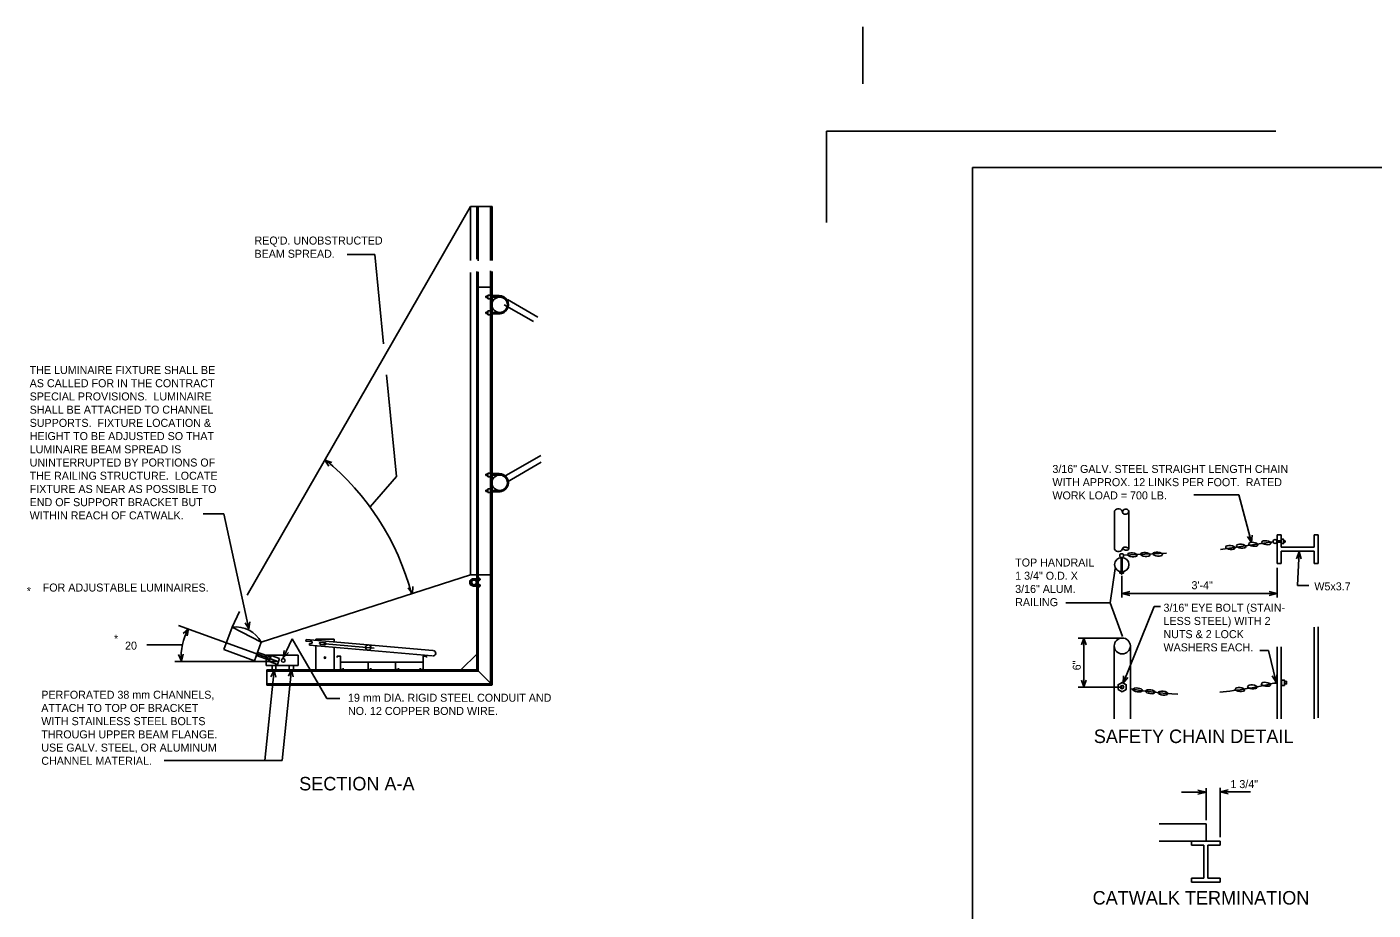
# Model space of a CAD drawing. Extents: x 2472.79 to 2482.44, y 2457.5 to 2462.64.
# Drawn here: x 2472.791 to 2476.659, y 2460.096 to 2462.635 of the extents above; entities that cross this region are included whole.
import ezdxf

# ---------------------------------------------------------------- set-up
doc = ezdxf.new("R2010")
doc.units = 0
doc.layers.add('Level 1', color=7, linetype='Continuous')
doc.layers.add('Level 2', color=7, linetype='Continuous')

msp = doc.modelspace()

# ---------------------------------------------------------------- linework, layer by layer
at = {"layer": 'Level 1'}
for p, q in [((2476.3796, 2462.3356), (2475.0881, 2462.3356)), ((2475.0881, 2462.3356), (2475.0881, 2462.0726)), ((2475.5081, 2457.8211), (2475.5081, 2462.2306)), ((2482.0963, 2462.2306), (2475.5081, 2462.2306)), ((2474.0655, 2462.1183), (2474.1272, 2462.1183)), ((2474.0655, 2461.963), (2474.0655, 2462.1183)), ((2474.0831, 2461.9676), (2474.0831, 2462.1183)), ((2474.0873, 2461.9621), (2474.0873, 2462.1183)), ((2474.1229, 2461.9639), (2474.1229, 2462.1183)), ((2474.1272, 2461.9639), (2474.1272, 2462.1183)), ((2474.0655, 2461.0599), (2474.0655, 2461.9292)), ((2474.0831, 2461.0599), (2474.0831, 2461.932)), ((2474.0873, 2461.0599), (2474.0873, 2461.9311)), ((2474.1229, 2461.0599), (2474.1229, 2461.9338)), ((2474.1272, 2461.0599), (2474.1272, 2461.932)), ((2474.083, 2460.787), (2474.083, 2461.8871)), ((2474.083, 2461.8871), (2474.1271, 2461.8871)), ((2474.0873, 2460.7828), (2474.0873, 2461.8871)), ((2474.109, 2461.8609), (2474.109, 2461.8567)), ((2474.109, 2461.8609), (2474.1155, 2461.8609)), ((2474.1155, 2461.8641), (2474.1216, 2461.8641)), ((2474.1155, 2461.8641), (2474.1155, 2461.8535)), ((2474.1229, 2460.7423), (2474.1229, 2461.8871)), ((2474.1257, 2461.8625), (2474.1477, 2461.8625)), ((2474.1271, 2460.7429), (2474.1271, 2461.8871)), ((2474.109, 2461.8567), (2474.1155, 2461.8567)), ((2474.1155, 2461.8535), (2474.1216, 2461.8535)), ((2474.1284, 2461.8583), (2474.1505, 2461.8583)), ((2474.1623, 2461.8359), (2474.2459, 2461.7877)), ((2474.1712, 2461.8512), (2474.2592, 2461.8004)), ((2474.109, 2461.8151), (2474.109, 2461.8109)), ((2474.109, 2461.8151), (2474.1155, 2461.8151)), ((2474.109, 2461.8109), (2474.1155, 2461.8109)), ((2474.1155, 2461.8183), (2474.1216, 2461.8183)), ((2474.1155, 2461.8183), (2474.1155, 2461.8077)), ((2474.1155, 2461.8077), (2474.1216, 2461.8077)), ((2474.1279, 2461.8099), (2474.1501, 2461.8099)), ((2474.1284, 2461.8142), (2474.1504, 2461.8142)), ((2474.1623, 2461.3422), (2474.2672, 2461.4027)), ((2474.1712, 2461.3269), (2474.2688, 2461.3833)), ((2474.109, 2461.3492), (2474.109, 2461.3449)), ((2474.109, 2461.3492), (2474.1155, 2461.3492)), ((2474.109, 2461.3449), (2474.1155, 2461.3449)), ((2474.1155, 2461.3523), (2474.1216, 2461.3523)), ((2474.1155, 2461.3523), (2474.1155, 2461.3418)), ((2474.1155, 2461.3418), (2474.1216, 2461.3418)), ((2474.1257, 2461.3507), (2474.1477, 2461.3507)), ((2474.1284, 2461.3465), (2474.1505, 2461.3465)), ((2474.109, 2461.3034), (2474.109, 2461.2991)), ((2474.109, 2461.3034), (2474.1155, 2461.3034)), ((2474.109, 2461.2991), (2474.1155, 2461.2991)), ((2474.1155, 2461.3066), (2474.1216, 2461.3066)), ((2474.1155, 2461.3066), (2474.1155, 2461.296)), ((2474.1155, 2461.296), (2474.1216, 2461.296)), ((2474.1279, 2461.2982), (2474.1501, 2461.2982)), ((2474.1284, 2461.3024), (2474.1504, 2461.3024)), ((2475.9161, 2461.1331), (2475.9161, 2461.2433)), ((2475.9572, 2461.1331), (2475.9572, 2461.2417)), ((2476.3837, 2461.092), (2476.3837, 2461.1743)), ((2476.395, 2461.1743), (2476.3837, 2461.1743)), ((2476.395, 2461.1743), (2476.395, 2461.139)), ((2476.5014, 2461.1743), (2476.4901, 2461.1743)), ((2476.4901, 2461.1743), (2476.4901, 2461.139)), ((2476.5014, 2461.092), (2476.5014, 2461.1743)), ((2476.3825, 2461.157), (2476.3951, 2461.157)), ((2476.3825, 2461.1533), (2476.3949, 2461.1533)), ((2476.4901, 2461.139), (2476.395, 2461.139)), ((2476.395, 2461.092), (2476.395, 2461.1273)), ((2476.4901, 2461.1273), (2476.395, 2461.1273)), ((2476.4067, 2461.157), (2476.4016, 2461.157)), ((2476.4067, 2461.1533), (2476.402, 2461.1533)), ((2476.4067, 2461.157), (2476.4067, 2461.1533)), ((2476.4901, 2461.092), (2476.4901, 2461.1273)), ((2475.935, 2461.1094), (2475.935, 2461.0688)), ((2475.9381, 2461.1089), (2475.9381, 2461.0683)), ((2476.395, 2461.092), (2476.3837, 2461.092)), ((2476.5014, 2461.092), (2476.4901, 2461.092)), ((2474.0655, 2461.0599), (2474.1272, 2461.0599)), ((2474.0742, 2461.0485), (2474.083, 2461.0485)), ((2474.083, 2460.7958), (2474.083, 2461.0589)), ((2474.0901, 2461.051), (2474.0873, 2461.051)), ((2474.0901, 2461.051), (2474.0901, 2461.0424)), ((2474.0931, 2461.0485), (2474.0901, 2461.0485)), ((2474.0931, 2461.0485), (2474.0931, 2461.0454)), ((2474.0742, 2461.0454), (2474.083, 2461.0454)), ((2474.0742, 2461.0305), (2474.083, 2461.0305)), ((2474.0742, 2461.0273), (2474.083, 2461.0273)), ((2474.0901, 2461.0424), (2474.0855, 2461.0424)), ((2474.0901, 2461.0243), (2474.0855, 2461.0243)), ((2474.0901, 2461.0331), (2474.0856, 2461.0331)), ((2474.0931, 2461.0454), (2474.0901, 2461.0454)), ((2474.0901, 2461.0243), (2474.0901, 2461.0331)), ((2474.0931, 2461.0305), (2474.0901, 2461.0305)), ((2474.0931, 2461.0273), (2474.0901, 2461.0273)), ((2474.0931, 2461.0273), (2474.0931, 2461.0305)), ((2473.3564, 2460.8445), (2473.38, 2460.9093)), ((2473.4639, 2460.8656), (2473.38, 2460.9093)), ((2476.4901, 2460.6455), (2476.4901, 2460.9089)), ((2476.5014, 2460.6484), (2476.5014, 2460.9104)), ((2473.4445, 2460.8125), (2473.4639, 2460.8656)), ((2473.593, 2460.8739), (2473.5925, 2460.869)), ((2473.6079, 2460.8676), (2473.5925, 2460.869)), ((2473.593, 2460.8739), (2473.9567, 2460.8421)), ((2473.603, 2460.8625), (2473.6026, 2460.8576)), ((2473.6026, 2460.8576), (2473.9553, 2460.8267)), ((2473.6208, 2460.8746), (2473.655, 2460.8746)), ((2473.6208, 2460.8746), (2473.649, 2460.8746)), ((2473.6208, 2460.8746), (2473.6396, 2460.8746)), ((2473.6208, 2460.8746), (2473.6208, 2460.8713)), ((2473.6208, 2460.7864), (2473.6208, 2460.8557)), ((2473.6737, 2460.8746), (2473.655, 2460.8746)), ((2473.6737, 2460.8746), (2473.655, 2460.8746)), ((2473.6737, 2460.8746), (2473.6737, 2460.867)), ((2475.9151, 2460.6455), (2475.9151, 2460.8552)), ((2475.9151, 2460.6455), (2475.9151, 2460.8552)), ((2475.9614, 2460.6455), (2475.9614, 2460.8552)), ((2473.4445, 2460.8125), (2473.3564, 2460.8445)), ((2473.4874, 2460.8141), (2473.4502, 2460.8276)), ((2473.4903, 2460.8235), (2473.4539, 2460.8367)), ((2473.4785, 2460.8287), (2473.5698, 2460.8287)), ((2473.4785, 2460.7994), (2473.4785, 2460.8287)), ((2473.4868, 2460.8109), (2473.4929, 2460.8275)), ((2473.5166, 2460.8189), (2473.4929, 2460.8275)), ((2473.5105, 2460.8023), (2473.5166, 2460.8189)), ((2473.5698, 2460.7994), (2473.5698, 2460.8287)), ((2473.6737, 2460.7864), (2473.6737, 2460.8514)), ((2474.083, 2460.8311), (2474.0389, 2460.787)), ((2476.3837, 2460.6455), (2476.3837, 2460.8529)), ((2476.395, 2460.6455), (2476.395, 2460.8529)), ((2473.4785, 2460.7994), (2473.5698, 2460.7994)), ((2473.4796, 2460.7864), (2474.083, 2460.7864)), ((2473.4796, 2460.7423), (2473.4796, 2460.7864)), ((2473.4796, 2460.7822), (2474.0873, 2460.7822)), ((2473.5105, 2460.8023), (2473.4868, 2460.8109)), ((2473.4949, 2460.7865), (2473.4949, 2460.7994)), ((2473.506, 2460.7865), (2473.506, 2460.7994)), ((2473.5444, 2460.7865), (2473.5444, 2460.7994)), ((2473.5562, 2460.7865), (2473.5562, 2460.7994)), ((2473.6913, 2460.8085), (2473.9296, 2460.8085)), ((2473.9037, 2460.7864), (2473.983, 2460.7864)), ((2473.9037, 2460.7822), (2474.0178, 2460.7822)), ((2474.083, 2460.787), (2474.1271, 2460.7429)), ((2473.4796, 2460.7466), (2474.1229, 2460.7466)), ((2473.4796, 2460.7423), (2474.1271, 2460.7423)), ((2476.3837, 2460.7483), (2476.3736, 2460.7483)), ((2476.1368, 2460.3435), (2476.0442, 2460.3435)), ((2476.1368, 2460.3435), (2476.1797, 2460.3435)), ((2476.1368, 2460.2934), (2476.0442, 2460.2934)), ((2476.1368, 2460.2934), (2476.1368, 2460.2821)), ((2476.2192, 2460.2934), (2476.1368, 2460.2934)), ((2476.1368, 2460.2821), (2476.1722, 2460.2821)), ((2476.1722, 2460.2821), (2476.1722, 2460.187)), ((2476.2192, 2460.2821), (2476.1839, 2460.2821)), ((2476.1839, 2460.2821), (2476.1839, 2460.187)), ((2476.2192, 2460.2934), (2476.2192, 2460.2821)), ((2476.1368, 2460.187), (2476.1368, 2460.1758)), ((2476.1368, 2460.187), (2476.1722, 2460.187)), ((2476.2192, 2460.1758), (2476.1368, 2460.1758)), ((2476.2192, 2460.187), (2476.1839, 2460.187)), ((2476.2192, 2460.187), (2476.2192, 2460.1758))]:
    msp.add_line(p, q, dxfattribs=at)
for points in [[(2476.3949, 2461.1497), (2476.4018, 2461.1497), (2476.4018, 2461.1618), (2476.3949, 2461.1618)], [(2475.9309, 2461.0687), (2475.9419, 2461.0687), (2475.9419, 2461.0645), (2475.9309, 2461.0645)], [(2475.9346, 2461.0683), (2475.9389, 2461.0683), (2475.9389, 2461.0683), (2475.9346, 2461.0683)], [(2475.9376, 2460.7233), (2475.9494, 2460.7299), (2475.9496, 2460.7434), (2475.938, 2460.7504), (2475.9262, 2460.7438), (2475.926, 2460.7302)], [(2476.3956, 2460.7415), (2476.4044, 2460.7415), (2476.4044, 2460.7571), (2476.3956, 2460.7571)], [(2476.4046, 2460.7461), (2476.4105, 2460.7461), (2476.4105, 2460.7534), (2476.4046, 2460.7534)]]:
    msp.add_lwpolyline(points, close=True, dxfattribs=at)
for points in [[(2475.9408, 2461.1165), (2476.0656, 2461.1215)], [(2475.9356, 2461.0642), (2475.9356, 2461.062), (2475.9374, 2461.062), (2475.9374, 2461.0642)], [(2473.6913, 2460.8085), (2473.6913, 2460.8261), (2473.6826, 2460.8261), (2473.6826, 2460.8219)], [(2473.9296, 2460.8085), (2473.9296, 2460.8261), (2473.9384, 2460.8261), (2473.9384, 2460.8219)], [(2473.6913, 2460.8085), (2473.6913, 2460.787), (2473.6998, 2460.787), (2473.6998, 2460.7912)], [(2473.6913, 2460.8085), (2473.6913, 2460.787), (2473.6998, 2460.787), (2473.6998, 2460.7912)], [(2473.7708, 2460.8085), (2473.7708, 2460.787), (2473.7792, 2460.787), (2473.7792, 2460.7912)], [(2473.8502, 2460.8085), (2473.8502, 2460.787), (2473.8586, 2460.787), (2473.8586, 2460.7912)], [(2473.9296, 2460.8085), (2473.9296, 2460.787), (2473.9211, 2460.787), (2473.9211, 2460.7912)]]:
    msp.add_lwpolyline(points, dxfattribs=at)
for centre, major_axis, start_param, end_param in [((2474.1477, 2461.8362), (-0.0263, 0), 1.570796, 4.712389), ((2474.1492, 2461.8362), (-0.0221, 0), 1.570796, 4.712389), ((2474.1477, 2461.3245), (-0.0263, 0), 1.570796, 4.712389), ((2474.1492, 2461.3245), (-0.0221, 0), 1.570796, 4.712389), ((2475.9267, 2461.2382), (-0.0118, 0), 3.176119, 5.840553), ((2475.948, 2461.2391), (0.00957, 0), 0.273424, 3.195008), ((2475.9473, 2461.2436), (-0.0101, 0), 0.517939, 2.950494), ((2475.9271, 2461.1386), (-0.0123, 0), 0.467275, 2.979388), ((2475.9467, 2461.1269), (-0.0122, 0), 3.667658, 5.365602), ((2475.9496, 2461.1417), (0.0116, 0), 3.600977, 5.432283), ((2474.0739, 2461.0379), (0.0106, 0), 1.542929, 4.740256), ((2474.0738, 2461.0379), (0.00745, 0), 1.515065, 4.76812), ((2473.3906, 2460.8274), (-0.0826, 0), 3.622274, 4.841499), ((2473.6077, 2460.8649), (-0.00275, 0), 1.48353, 4.625122), ((2475.9382, 2460.8548), (0.0232, 0), 0.01739, 3.126763), ((2475.9382, 2460.8548), (0.0232, 0), 0.01739, 3.126763), ((2475.9382, 2460.8556), (0.0232, 0), 3.156422, 6.265796), ((2473.9575, 2460.8344), (-0.00772, 0), 1.500919, 4.610293), ((2476.1329, 2461.7165), (-0.998, 0), 1.656478, 1.814374), ((2476.1433, 2461.7132), (-0.998, 0), 1.38791, 1.525517)]:
    msp.add_ellipse(centre, major_axis=major_axis, ratio=0.9996, start_param=start_param, end_param=end_param, dxfattribs=at)
for centre, major_axis, ratio in [((2474.1492, 2461.8362), (0.0221, 0), 0.9996), ((2474.1492, 2461.8362), (0.0221, 0), 0.9996), ((2474.1492, 2461.3245), (0.0221, 0), 0.9996), ((2474.1492, 2461.3245), (0.0221, 0), 0.9996), ((2476.0044, 2461.1181), (-0.0135, 0.0015), 0.412607), ((2476.0401, 2461.1189), (-0.0135, 0.0015), 0.412607), ((2476.2489, 2461.1382), (-0.0135, 0.0015), 0.412607), ((2476.2799, 2461.142), (-0.0135, 0.0015), 0.412607), ((2476.3149, 2461.1474), (-0.0135, 0.0015), 0.412607), ((2476.3522, 2461.1521), (-0.0135, 0.0015), 0.412607), ((2476.377, 2461.1554), (0.00548, 0), 0.9996), ((2475.9367, 2461.0889), (0.0206, 0), 0.9996), ((2475.9365, 2461.1149), (0.00548, 0), 0.9996), ((2475.9671, 2461.1173), (-0.0135, 0.0015), 0.412607), ((2474.0756, 2461.0379), (0.00662, 0), 0.9996), ((2473.6472, 2460.8614), (0.0022, 0), 0.9996), ((2473.6472, 2460.8614), (0.0022, 0), 0.9996), ((2473.5272, 2460.8135), (0.00525, 0), 0.9996), ((2473.6472, 2460.8213), (0.0022, 0), 0.9996), ((2475.9378, 2460.7368), (0.00485, 0), 0.9996), ((2476.3119, 2460.7374), (-0.0135, 0.0015), 0.412607), ((2476.351, 2460.7449), (-0.0135, 0.0015), 0.412607), ((2475.9825, 2460.7286), (-0.0135, 0.0015), 0.412607), ((2476.019, 2460.7236), (-0.0135, 0.0015), 0.412607), ((2476.0554, 2460.7194), (-0.0135, 0.0015), 0.412607), ((2476.2764, 2460.7301), (-0.0135, 0.0015), 0.412607)]:
    msp.add_ellipse(centre, major_axis=major_axis, ratio=ratio, dxfattribs=at)
at = {"layer": 'Level 2'}
for p, q in [((2475.1931, 2462.471), (2475.1931, 2462.6351)), ((2474.0655, 2462.1183), (2473.4238, 2461.0013)), ((2473.7107, 2461.9809), (2473.7899, 2461.9809)), ((2473.7899, 2461.9809), (2473.8153, 2461.7237)), ((2473.853, 2461.3425), (2473.8241, 2461.6348)), ((2473.6465, 2461.3891), (2473.6665, 2461.3827)), ((2473.6583, 2461.3717), (2473.6465, 2461.3891)), ((2473.853, 2461.3425), (2473.7766, 2461.2553)), ((2476.2729, 2461.2893), (2476.1438, 2461.2893)), ((2476.3098, 2461.1529), (2476.2729, 2461.2893)), ((2473.3566, 2461.2353), (2473.2967, 2461.2353)), ((2473.4287, 2460.9041), (2473.3566, 2461.2353)), ((2476.3098, 2461.1529), (2476.298, 2461.1703)), ((2476.3112, 2461.1738), (2476.3098, 2461.1529)), ((2476.4385, 2461.1061), (2476.4464, 2461.1256)), ((2476.4464, 2461.1256), (2476.4413, 2461.0287)), ((2476.4464, 2461.1256), (2476.4522, 2461.1054)), ((2473.4639, 2460.8656), (2474.0655, 2461.0599)), ((2475.9181, 2461.0777), (2475.9032, 2460.9791)), ((2475.9367, 2461.0566), (2475.9367, 2460.9943)), ((2476.3837, 2461.0802), (2476.3837, 2460.9943)), ((2473.8984, 2461.0054), (2473.886, 2461.0223)), ((2473.8991, 2461.0264), (2473.8984, 2461.0054)), ((2476.4413, 2461.0287), (2476.4745, 2461.0287)), ((2475.9032, 2460.9791), (2475.7758, 2460.9791)), ((2475.9032, 2460.9791), (2475.9389, 2460.8819)), ((2475.9367, 2461.0061), (2476.3837, 2461.0061)), ((2473.38, 2460.9093), (2473.4016, 2460.9545)), ((2475.9404, 2460.7485), (2476.0299, 2460.9689)), ((2476.0299, 2460.9689), (2476.0478, 2460.9689)), ((2473.5142, 2460.8095), (2473.2257, 2460.9144)), ((2473.2392, 2460.8908), (2473.255, 2460.9046)), ((2473.255, 2460.9046), (2473.2511, 2460.8839)), ((2473.4287, 2460.9041), (2473.4178, 2460.922)), ((2473.4312, 2460.9249), (2473.4287, 2460.9041)), ((2473.2375, 2460.8584), (2473.1351, 2460.8584)), ((2473.5274, 2460.8212), (2473.5526, 2460.8757)), ((2473.5526, 2460.8757), (2473.652, 2460.704)), ((2473.6074, 2460.8621), (2473.603, 2460.8625)), ((2473.6338, 2460.8598), (2473.647, 2460.8587)), ((2473.6343, 2460.8653), (2473.6475, 2460.8641)), ((2473.7881, 2460.8491), (2473.6472, 2460.8614)), ((2475.9378, 2460.878), (2475.8119, 2460.878)), ((2475.8207, 2460.8579), (2475.8276, 2460.8777)), ((2475.8276, 2460.8777), (2475.8276, 2460.7372)), ((2475.8276, 2460.8777), (2475.8345, 2460.8579)), ((2473.2346, 2460.8114), (2473.2259, 2460.8306)), ((2473.2396, 2460.8318), (2473.2346, 2460.8114)), ((2473.5274, 2460.8212), (2473.5295, 2460.8421)), ((2473.5419, 2460.8364), (2473.5274, 2460.8212)), ((2476.3587, 2460.8417), (2476.3334, 2460.8417)), ((2476.38, 2460.751), (2476.3587, 2460.8417)), ((2473.5081, 2460.8107), (2473.2155, 2460.8107)), ((2473.5007, 2460.7857), (2473.4738, 2460.5258)), ((2473.4884, 2460.7864), (2473.5985, 2460.7864)), ((2473.4918, 2460.7667), (2473.5007, 2460.7857)), ((2473.5007, 2460.7857), (2473.5055, 2460.7653)), ((2473.5512, 2460.7871), (2473.5242, 2460.5258)), ((2473.5423, 2460.768), (2473.5512, 2460.7871)), ((2473.5512, 2460.7871), (2473.556, 2460.7666)), ((2475.8276, 2460.7372), (2475.8207, 2460.7571)), ((2475.8345, 2460.7571), (2475.8276, 2460.7372)), ((2475.9404, 2460.7485), (2475.9415, 2460.7695)), ((2475.9543, 2460.7643), (2475.9404, 2460.7485)), ((2476.38, 2460.751), (2476.3688, 2460.7688)), ((2476.3821, 2460.772), (2476.38, 2460.751)), ((2473.652, 2460.704), (2473.6899, 2460.704)), ((2475.9378, 2460.7368), (2475.8119, 2460.7368)), ((2473.5242, 2460.5258), (2473.1852, 2460.5258)), ((2476.1086, 2460.4346), (2476.1792, 2460.4346)), ((2476.1792, 2460.3543), (2476.1792, 2460.4464)), ((2476.2192, 2460.3051), (2476.2192, 2460.4475)), ((2476.3067, 2460.4357), (2476.2192, 2460.4357)), ((2476.1797, 2460.3435), (2476.1797, 2460.2941))]:
    msp.add_line(p, q, dxfattribs=at)
for points in [[(2476.3712, 2461.1544), (2476.2209, 2461.1326)], [(2475.9602, 2461.0119), (2475.9367, 2461.0061), (2475.9602, 2461.0002)], [(2476.3602, 2461.0002), (2476.3837, 2461.0061), (2476.3602, 2461.0119)], [(2476.1556, 2460.4288), (2476.1792, 2460.4346), (2476.1556, 2460.4405)], [(2476.2427, 2460.4416), (2476.2192, 2460.4357), (2476.2427, 2460.4298)]]:
    msp.add_lwpolyline(points, dxfattribs=at)
for centre, major_axis, start_param, end_param in [((2473.1714, 2460.813), (0.7494, 0), 0.25922, 0.881794), ((2473.3922, 2460.8256), (-0.1583, 0), 5.760622, 6.373355), ((2473.634, 2460.8626), (0.00275, 0), 1.48353, 4.625122), ((2473.6472, 2460.8614), (-0.00275, 0), 1.48353, 4.625122), ((2473.7715, 2460.8505), (-0.00772, 0), 4.639952, 7.749326), ((2473.7713, 2460.8506), (-0.00772, 0), 1.500919, 4.610293), ((2473.7713, 2460.8506), (-0.00772, 0), 1.500919, 4.610293)]:
    msp.add_ellipse(centre, major_axis=major_axis, ratio=0.9996, start_param=start_param, end_param=end_param, dxfattribs=at)

# ---------------------------------------------------------------- texts
for s, height, p in [("REQ'D. UNOBSTRUCTED", 0.023, (2473.4446, 2462.0093)), ('BEAM SPREAD.', 0.023, (2473.4446, 2461.9713)), ('THE LUMINAIRE FIXTURE SHALL BE', 0.023, (2472.7985, 2461.6371)), ('AS CALLED FOR IN THE CONTRACT', 0.023, (2472.7985, 2461.5991)), ('SPECIAL PROVISIONS.  LUMINAIRE', 0.023, (2472.7985, 2461.5611)), ('SHALL BE ATTACHED TO CHANNEL', 0.023, (2472.7985, 2461.5231)), ('SUPPORTS.  FIXTURE LOCATION &', 0.023, (2472.7985, 2461.4851)), ('HEIGHT TO BE ADJUSTED SO THAT', 0.023, (2472.7985, 2461.4471)), ('LUMINAIRE BEAM SPREAD IS', 0.023, (2472.7985, 2461.4091)), ('UNINTERRUPTED BY PORTIONS OF', 0.023, (2472.7985, 2461.3711)), ('3/16" GALV. STEEL STRAIGHT LENGTH CHAIN', 0.023, (2475.7375, 2461.3526)), ('THE RAILING STRUCTURE.  LOCATE', 0.023, (2472.7985, 2461.3331)), ('FIXTURE AS NEAR AS POSSIBLE TO', 0.023, (2472.7985, 2461.2951)), ('WITH APPROX. 12 LINKS PER FOOT.  RATED', 0.023, (2475.7375, 2461.3146)), ('END OF SUPPORT BRACKET BUT', 0.023, (2472.7985, 2461.2571)), ('WORK LOAD = 700 LB.', 0.023, (2475.7375, 2461.2766)), ('WITHIN REACH OF CATWALK.', 0.023, (2472.7985, 2461.2191)), ('TOP HANDRAIL', 0.023, (2475.6305, 2461.0836)), ('1 3/4" O.D. X', 0.023, (2475.6305, 2461.0456)), ('*', 0.023, (2472.7901, 2461.0016)), ('FOR ADJUSTABLE LUMINAIRES.', 0.023, (2472.836, 2461.0116)), ('3/16" ALUM.', 0.023, (2475.6305, 2461.0076)), ('3\'-4"', 0.023, (2476.1372, 2461.0183)), ('W5x3.7', 0.023, (2476.4902, 2461.015)), ('RAILING', 0.023, (2475.6305, 2460.9696)), ('3/16" EYE BOLT (STAIN-', 0.023, (2476.0567, 2460.9536)), ('LESS STEEL) WITH 2', 0.023, (2476.0567, 2460.9156)), ('NUTS & 2 LOCK', 0.023, (2476.0567, 2460.8776)), ('*', 0.023, (2473.0409, 2460.8645)), ('20', 0.023, (2473.0726, 2460.8446)), ('WASHERS EACH.', 0.023, (2476.0567, 2460.8396)), ('PERFORATED 38 mm CHANNELS,', 0.023, (2472.8319, 2460.7034)), ('19 mm DIA. RIGID STEEL CONDUIT AND', 0.023, (2473.7132, 2460.6948)), ('ATTACH TO TOP OF BRACKET', 0.023, (2472.8319, 2460.6654)), ('NO. 12 COPPER BOND WIRE.', 0.023, (2473.7132, 2460.6568)), ('WITH STAINLESS STEEL BOLTS', 0.023, (2472.8319, 2460.6274)), ('THROUGH UPPER BEAM FLANGE.', 0.023, (2472.8319, 2460.5894)), ('USE GALV. STEEL, OR ALUMINUM', 0.023, (2472.8319, 2460.5514)), ('CHANNEL MATERIAL.', 0.023, (2472.8319, 2460.5134)), ('SECTION A-A', 0.0388, (2473.573, 2460.4398)), ('1 3/4"', 0.023, (2476.249, 2460.4464)), ('CATWALK TERMINATION', 0.0388, (2475.8531, 2460.1117))]:
    msp.add_text(s, height=height, dxfattribs=at).set_placement(p)
for s, height, rotation, p in [('6"', 0.023, 90, (2475.819, 2460.7851)), ('SAFETY CHAIN DETAIL', 0.0388, 360, (2475.8565, 2460.576))]:
    msp.add_text(s, height=height, rotation=rotation, dxfattribs=at).set_placement(p)

doc.saveas('drawing.dxf')
